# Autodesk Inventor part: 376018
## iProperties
Company: Mayer & Müller Schaltgeräte
Created: 2005-06
Part Number: 376018
Material: Viton - schwarz
Document SubType Name: Modeling
Designer: I.Baliuc
Manufacturer: Standard
Standards Organization: Custom
Description: Balg
Vendor: Viton
Density: 0.93 g/cm^3
Author: T.Messerschmitt
Revision Number: 376018
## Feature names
1. Drehung1 [Revolution]
2. Spiegeln1 [Mirror]
3. Rundung3 [Fillet]
4. Rundung4 [Fillet]
